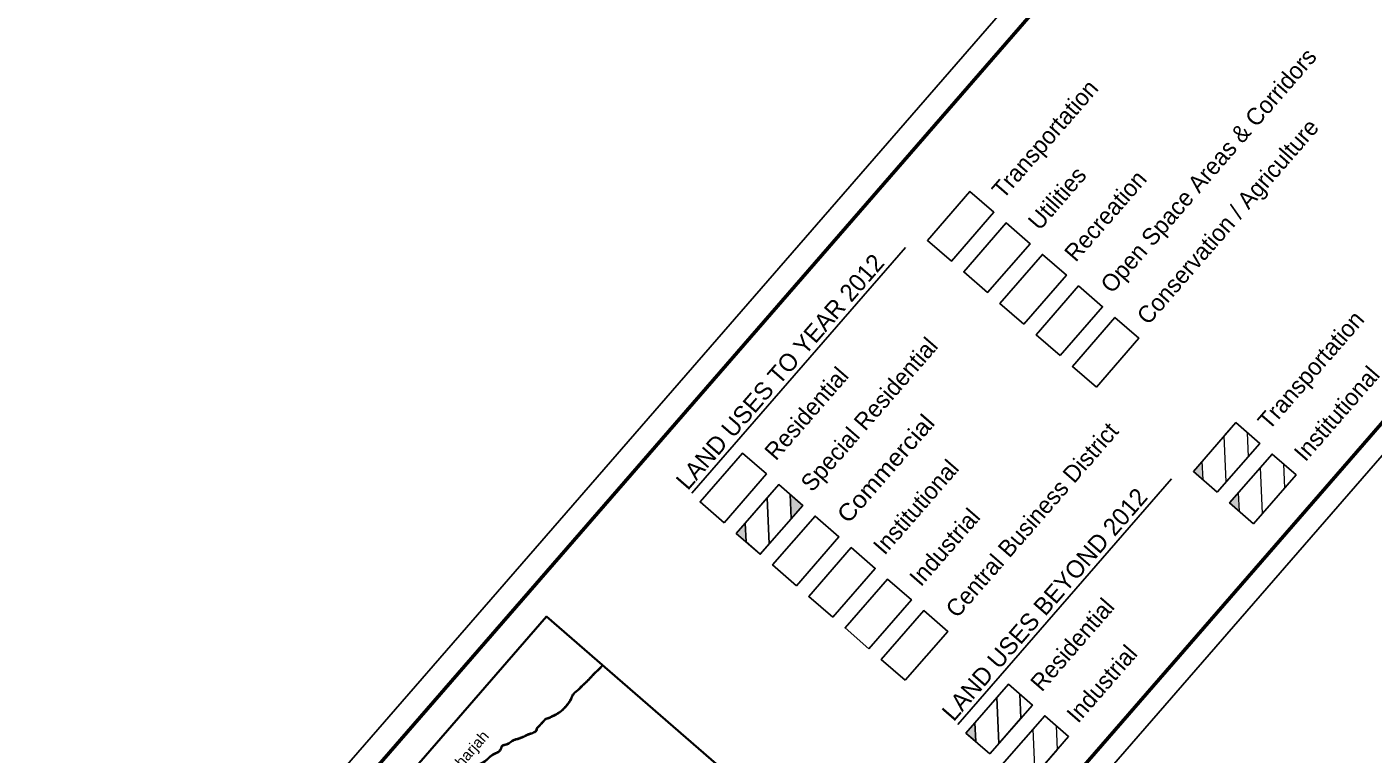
# Model space of a CAD drawing. Extents: x 290038 to 370218, y 2722677 to 2808586.
# Drawn here: x 312746 to 335265, y 2733950 to 2746123 of the extents above; entities that cross this region are included whole.
import ezdxf

# ---------------------------------------------------------------- set-up
doc = ezdxf.new("R2010")
doc.units = 0
doc.header["$LTSCALE"] = 88
for name, color, linetype, lineweight in [('20', 7, 'Continuous', 13), ('25', 7, 'Continuous', 13), ('26', 7, 'Continuous', 13), ('36', 7, 'Continuous', 35), ('6', 7, 'Continuous', 13)]:
    doc.layers.add(name, color=color, linetype=linetype, lineweight=lineweight)

msp = doc.modelspace()

# ---------------------------------------------------------------- hatches: boundary and pattern name
at = {"layer": '20'}
for points in [[(332436.45, 2738538.81), (332422.57, 2738852.87), (332273.04, 2738680.86)], [(325540.2, 2737891.82), (325522.27, 2738297.3), (325733.25, 2738113.9)], [(333043.08, 2738011.47), (333029.2, 2738325.54), (332879.68, 2738153.52)], [(324785.24, 2737502.01), (324771.35, 2737816.07), (324621.83, 2737644.06)], [(328629.91, 2734159.89), (328616.03, 2734473.95), (328466.5, 2734301.94)]]:
    msp.add_hatch(color=256, dxfattribs=at).paths.add_polyline_path(points)

# ---------------------------------------------------------------- linework, layer by layer
at = {"layer": '20', "lineweight": 25}
for p, q in [((323878.58, 2738316.3), (327453.25, 2742428.49)), ((328329.89, 2734446.84), (331904.56, 2738559.03))]:
    msp.add_line(p, q, dxfattribs=at)
for points in [[(313980.4, 2729027.31), (362912.77, 2785317.56), (370218.38, 2778966.9), (321286.01, 2722676.64)], [(328222.16, 2742202.25), (328933.16, 2743020.16), (328532.74, 2743368.24), (327821.74, 2742550.32)], [(328828.79, 2741674.91), (329539.79, 2742492.83), (329139.38, 2742840.9), (328428.37, 2742022.98)], [(329435.42, 2741147.57), (330146.43, 2741965.49), (329746.01, 2742313.57), (329035, 2741495.65)], [(330042.05, 2740620.23), (330753.06, 2741438.15), (330352.64, 2741786.23), (329641.64, 2740968.31)], [(330648.69, 2740092.9), (331359.69, 2740910.81), (330959.27, 2741258.89), (330248.27, 2740440.97)], [(332673.46, 2738332.79), (333384.47, 2739150.7), (332984.05, 2739498.78), (332273.04, 2738680.86)], [(324415.61, 2737823.32), (325126.62, 2738641.24), (324726.2, 2738989.32), (324015.2, 2738171.4)], [(324415.61, 2737823.32), (325126.62, 2738641.24), (324726.2, 2738989.32), (324015.2, 2738171.4)], [(333280.09, 2737805.45), (333991.1, 2738623.37), (333590.68, 2738971.44), (332879.68, 2738153.53)], [(325022.25, 2737295.98), (325733.25, 2738113.9), (325332.83, 2738461.98), (324621.83, 2737644.06)], [(325022.25, 2737295.98), (325733.25, 2738113.9), (325332.83, 2738461.98), (324621.83, 2737644.06)], [(324785.24, 2737502.01), (324771.35, 2737816.07), (325138.77, 2738238.73), (325172.79, 2737469.16), (325022.25, 2737295.98)], [(325540.2, 2737891.82), (325522.27, 2738297.3), (325733.25, 2738113.9)], [(325628.88, 2736768.65), (326339.89, 2737586.56), (325939.47, 2737934.64), (325228.46, 2737116.72)], [(326235.51, 2736241.31), (326946.52, 2737059.23), (326546.1, 2737407.3), (325835.1, 2736589.39)], [(326842.15, 2735713.97), (327553.15, 2736531.89), (327152.73, 2736879.97), (326441.73, 2736062.05)], [(327448.78, 2735186.63), (328159.78, 2736004.55), (327759.37, 2736352.63), (327048.36, 2735534.71)], [(321270.19, 2723900.42), (327462.36, 2731023.7), (321446.7, 2736253.03), (315254.53, 2729129.75)], [(328866.92, 2733953.86), (329577.92, 2734771.78), (329177.51, 2735119.86), (328466.5, 2734301.94)], [(329017.46, 2734127.04), (328983.44, 2734896.61), (329177.51, 2735119.86), (329366.95, 2734955.18), (329384.87, 2734549.7)], [(329473.55, 2733426.52), (330184.56, 2734244.44), (329784.14, 2734592.52), (329073.14, 2733774.6)], [(328629.91, 2734159.89), (328616.03, 2734473.95), (328466.5, 2734301.94)]]:
    msp.add_lwpolyline(points, close=True, dxfattribs=at)
at = {"layer": '20', "lineweight": 53}
msp.add_lwpolyline([(314544.71, 2729066.77), (349767.76, 2769586.26), (356498.65, 2763735.18), (321275.6, 2723215.69)], close=True, dxfattribs=at)
at = {"layer": '20'}
for points in [[(328222.16, 2742202.25), (328933.16, 2743020.16), (328532.74, 2743368.24), (327821.74, 2742550.32)], [(328828.79, 2741674.91), (329539.79, 2742492.83), (329139.38, 2742840.9), (328428.37, 2742022.98)], [(329435.42, 2741147.57), (329035, 2741495.65), (329746.01, 2742313.57), (330146.43, 2741965.49)], [(330753.06, 2741438.15), (330042.05, 2740620.23), (329641.64, 2740968.31), (330352.64, 2741786.23)], [(331359.69, 2740910.81), (330648.69, 2740092.9), (330248.27, 2740440.97), (330959.27, 2741258.89)], [(332824, 2738505.96), (332789.98, 2739275.53), (332984.05, 2739498.78), (333173.49, 2739334.11), (333191.41, 2738928.62)], [(332436.45, 2738538.81), (332422.57, 2738852.87), (332273.04, 2738680.86)], [(333430.63, 2737978.63), (333396.62, 2738748.19), (333590.68, 2738971.44), (333780.12, 2738806.77), (333798.04, 2738401.28)], [(325172.79, 2737469.16), (325138.77, 2738238.73), (325332.83, 2738461.98), (325522.27, 2738297.3), (325540.2, 2737891.82)], [(333043.08, 2738011.47), (333029.2, 2738325.54), (332879.68, 2738153.52)], [(325628.88, 2736768.65), (325228.46, 2737116.72), (325939.47, 2737934.64), (326339.89, 2737586.57)], [(324785.24, 2737502.01), (324771.35, 2737816.07), (324621.83, 2737644.06)], [(326946.52, 2737059.23), (326235.51, 2736241.31), (325835.09, 2736589.39), (326546.1, 2737407.3)], [(327553.15, 2736531.89), (326842.15, 2735713.97), (326441.73, 2736062.05), (327152.73, 2736879.97)], [(328159.78, 2736004.55), (327448.78, 2735186.64), (327048.36, 2735534.71), (327759.37, 2736352.63)], [(329624.09, 2733599.7), (329590.07, 2734369.27), (329784.14, 2734592.52), (329973.58, 2734427.84), (329991.5, 2734022.36)]]:
    msp.add_lwpolyline(points, close=True, dxfattribs=at)
at = {"layer": '26'}
msp.add_arc((297079.42, 2769097.74), 26252.07, 291.9132, 316.68629, dxfattribs=at)
at = {"layer": '36'}
for points in [[(319132.95, 2733370.83), (319421.64, 2733392.92), (319442.69, 2733394.12), (319469.94, 2733400.54), (319519.9, 2733422.06), (319622.15, 2733452.24), (319737.05, 2733474.21), (319828.52, 2733494.02), (319957.6, 2733552.53), (320057.24, 2733600.44), (320155.59, 2733671.01), (320289.14, 2733765.51), (320416.91, 2733832.88), (320506.53, 2733914.33), (320590.55, 2733965.41), (320655.87, 2734002.43), (320673.16, 2734026.97), (320683.4, 2734047.04), (320696.82, 2734082.73), (320748.21, 2734107.59), (320804.06, 2734125.38), (320863.39, 2734167.74), (320917.93, 2734194.4), (320975.58, 2734209.05), (321034.39, 2734231.88), (321078.81, 2734250.65), (321144.41, 2734282.81), (321208.26, 2734302.69), (321244.49, 2734322.62), (321273.31, 2734344.56), (321279.58, 2734377.41), (321300.02, 2734403.75), (321336.96, 2734439.97), (321360.64, 2734466.5), (321397.4, 2734505.95), (321432.05, 2734539.6), (321465.5, 2734551.25), (321497.34, 2734562.81), (321527.28, 2734579.13), (321574.08, 2734598.85), (321620.43, 2734626.66), (321666.78, 2734654.48), (321720.22, 2734700.57), (321770.82, 2734753.8), (321810.18, 2734804.78), (321840.28, 2734847.1), (321867.57, 2734910.39), (321912.58, 2734976.31), (321966.11, 2735020.78), (322031.5, 2735085.42), (322087.05, 2735137.31), (322142.51, 2735190.82), (322194.54, 2735247.39), (322246.58, 2735303.96), (322312.24, 2735363.74), (322373.63, 2735427.34), (322383.92, 2735438.32)], [(319133.2, 2733367.56), (319421.86, 2733389.65), (319443.17, 2733390.86), (319470.98, 2733397.42), (319521.01, 2733418.97), (319622.93, 2733449.05), (319737.71, 2733470.99), (319829.56, 2733490.89), (319958.99, 2733549.56), (320058.91, 2733597.6), (320157.49, 2733668.34), (320290.86, 2733762.71), (320418.81, 2733830.18), (320508.5, 2733911.69), (320592.21, 2733962.58), (320658.12, 2733999.94), (320675.98, 2734025.27), (320686.41, 2734045.72), (320699.43, 2734080.35), (320749.43, 2734104.53), (320805.54, 2734122.41), (320865.08, 2734164.92), (320919.06, 2734191.3), (320976.58, 2734205.92), (321035.62, 2734228.84), (321080.17, 2734247.67), (321145.62, 2734279.76), (321209.55, 2734299.65), (321246.29, 2734319.86), (321276.29, 2734342.71), (321282.65, 2734376.02), (321302.47, 2734401.57), (321339.33, 2734437.7), (321363.06, 2734464.29), (321399.74, 2734503.66), (321433.81, 2734536.74), (321466.6, 2734548.16), (321498.69, 2734559.81), (321528.7, 2734576.17), (321575.57, 2734595.91), (321622.12, 2734623.85), (321668.71, 2734651.81), (321722.49, 2734698.19), (321773.31, 2734751.67), (321812.82, 2734802.82), (321843.15, 2734845.49), (321870.46, 2734908.8), (321915.03, 2734974.08), (321968.32, 2735018.34), (322033.78, 2735083.05), (322089.31, 2735134.93), (322144.86, 2735188.53), (322196.96, 2735245.17), (322248.9, 2735301.63), (322314.53, 2735361.39), (322376.01, 2735425.09), (322386.4, 2735436.17)]]:
    msp.add_spline(points, degree=3, dxfattribs=at)
at = {"layer": '6', "lineweight": 35}
msp.add_lwpolyline([(321270.19, 2723900.42), (327462.36, 2731023.7), (321446.7, 2736253.03), (315254.53, 2729129.75)], close=True, dxfattribs=at)

# ---------------------------------------------------------------- texts
at = {"layer": '20'}
for s, height, p in [('Open Space Areas & Corridors', 285, (330910.29, 2741645.14)), ('Transportation', 285, (329090.39, 2743227.15)), ('Conservation / Agriculture', 285, (331516.92, 2741117.8)), ('Utilities', 285, (329697.02, 2742699.81)), ('Recreation', 285, (330303.66, 2742172.47)), ('LAND USES TO YEAR 2012', 293.9, (323808.91, 2738350.72)), ('Transportation', 285, (333541.7, 2739357.69)), ('Special Residential', 285, (325890.48, 2738320.89)), ('Residential', 285, (325283.85, 2738848.22)), ('Institutional', 285, (334148.33, 2738830.35)), ('Central Business District', 285, (328317.01, 2736211.54)), ('Institutional', 285, (327103.75, 2737266.21)), ('LAND USES BEYOND 2012', 293.9, (328260.22, 2734481.26)), ('Industrial', 285, (327710.38, 2736738.88)), ('Residential', 285, (329735.16, 2734978.77)), ('Industrial', 285, (330341.79, 2734451.43))]:
    msp.add_text(s, height=height, rotation=49, dxfattribs=at).set_placement(p)
at = {"layer": '20', "width": 1.1}
msp.add_text('Commercial', height=285, rotation=49, dxfattribs=at).set_placement((326497.12, 2737793.55))
at = {"layer": '25', "width": 1.05}
msp.add_text('Sharjah', height=180, rotation=49, dxfattribs=at).set_placement((319921.79, 2733587.73))

doc.saveas('drawing.dxf')
